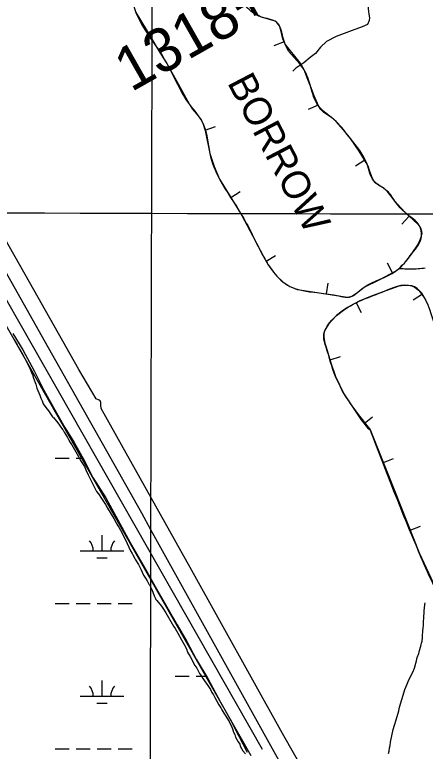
# Model space of a CAD drawing. Extents: x 3177185 to 3215018, y 812988 to 838321.
# Drawn here: x 3191526 to 3192464, y 823203 to 824888 of the extents above; entities that cross this region are included whole.
import ezdxf

# ---------------------------------------------------------------- set-up
doc = ezdxf.new("R2010")
doc.units = 0
for name, color, linetype in [('V-BORW-IDEN', 7, 'Continuous'), ('V-BORW-LINE', 7, 'Continuous'), ('V-GRID-MAJR', 7, 'Continuous'), ('V-ROAD-CNTR', 7, 'Continuous'), ('V-SITE-VEGE', 7, 'Continuous'), ('V-SURV-IDEN', 7, 'Continuous'), ('V-TOPO-SHOR', 7, 'Continuous'), ('V-WETL-SWMP', 7, 'Continuous')]:
    doc.layers.add(name, color=color, linetype=linetype)

msp = doc.modelspace()

# ---------------------------------------------------------------- linework, layer by layer
at = {"layer": 'V-BORW-LINE'}
for p, q in [((3192141.393, 824826.683), (3192118.318, 824817.063)), ((3191878.114, 824768.1410000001), (3191899.912, 824780.382)), ((3192219.4050000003, 824681.253), (3192196.271, 824671.777)), ((3191961.091, 824624.482), (3191984.752, 824632.554)), ((3192325.955, 824555.2490000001), (3192304.648, 824542.172)), ((3192019.5810000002, 824470.2930000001), (3192040.762, 824483.573)), ((3192427.292, 824427.59), (3192410.443, 824409.121)), ((3192100.417, 824324.746), (3192121.884, 824337.56)), ((3192389.773, 824297.56), (3192378.131, 824319.684)), ((3192238.593, 824249.332), (3192242.319, 824274.0530000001)), ((3192457.967, 824248.6140000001), (3192437.011, 824234.982)), ((3192306.193, 824228.922), (3192318.008, 824206.89)), ((3192246.517, 824098.697), (3192270.387, 824106.13)), ((3192324.406, 823952.698), (3192343.738, 823968.55)), ((3192368.48, 823863.686), (3192391.6720000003, 823873.02)), ((3192430.092, 823708.898), (3192453.344, 823718.082))]:
    msp.add_line(p, q, dxfattribs=at)
for points in [[(3191802.893, 824893.649), (3191825.791, 824854.311), (3191849.315, 824815.3250000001), (3191861.311, 824796.055), (3191873.268, 824776.77), (3191899.437, 824730.169), (3191924.8910000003, 824683.207), (3191932.312, 824672.331), (3191944.924, 824656.929), (3191950.79, 824648.942), (3191955.682, 824640.335), (3191961.438, 824623.463), (3191971.713, 824570.679), (3191981.668, 824540.805), (3191994.094, 824511.837), (3192019.5330000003, 824470.3690000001), (3192045.276, 824429.312), (3192070.1550000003, 824381.653), (3192094.983, 824333.85), (3192105.403, 824316.394), (3192117.092, 824299.568), (3192125.1580000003, 824289.786), (3192139.005, 824277.0040000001), (3192155.042, 824266.5210000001), (3192165.957, 824261.595), (3192171.576, 824259.8640000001), (3192177.336, 824258.661), (3192221.954, 824251.84), (3192266.571, 824245.115), (3192276.3370000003, 824243.235), (3192286.058, 824241.897), (3192291.34, 824242.404), (3192299.951, 824246.201), (3192324.307, 824264.608), (3192360.5870000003, 824282.201), (3192396.65, 824301.179), (3192407.774, 824309.734), (3192421.749, 824325.3960000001), (3192434.708, 824342.899), (3192447.285, 824362.088), (3192452.24, 824371.969), (3192456.06, 824382.018), (3192456.992, 824387.93), (3192456.661, 824392.655), (3192454.583, 824399.6240000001), (3192452.862, 824402.833), (3192450.704, 824405.7220000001), (3192435.805, 824419.824), (3192421.022, 824433.31), (3192407.884, 824447.405), (3192394.965, 824461.7170000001), (3192386.112, 824473.164), (3192377.455, 824484.7270000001), (3192370.258, 824491.023), (3192357.532, 824498.556), (3192351.585, 824502.735), (3192346.703, 824507.969), (3192341.919, 824517.18), (3192337.146, 824532.232), (3192334.609, 824539.6780000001), (3192331.216, 824546.6780000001), (3192312.982, 824576.385), (3192293.082, 824605.185), (3192277.036, 824625.013), (3192260.259, 824644.0800000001), (3192249.8850000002, 824653.022)], [(3192249.8850000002, 824653.022), (3192232.624, 824664.931), (3192225.2260000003, 824671.751), (3192219.879, 824680.096), (3192210.6550000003, 824702.618), (3192201.764, 824725.246), (3192194.538, 824743.696), (3192187.275, 824762.1290000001), (3192178.468, 824778.0210000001), (3192143.806, 824820.8960000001), (3192138.727, 824833.079), (3192134.148, 824853.208), (3192130.693, 824862.671), (3192124.899, 824870.849), (3192120.969, 824873.873), (3192087.455, 824883.493), (3192070.43, 824894.555)], [(3192467.754, 824230.1900000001), (3192462.112, 824242.243), (3192456.491, 824250.883), (3192446.075, 824261.6730000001), (3192440.066, 824265.508), (3192433.582, 824267.9450000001), (3192416.849, 824269.091), (3192403.916, 824266.938), (3192365.528, 824253.63), (3192339.108, 824243.687), (3192313.008, 824232.577), (3192286.514, 824218.3690000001), (3192273.998, 824209.811), (3192261.659, 824199.732), (3192250.451, 824189.012), (3192242.9590000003, 824180.3250000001)], [(3192242.9590000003, 824180.3250000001), (3192234.754, 824166.36), (3192232.614, 824158.997), (3192232.149, 824151.405), (3192232.845, 824145.559), (3192234.859, 824136.724), (3192237.406, 824127.957), (3192247.975, 824094.017), (3192259.282, 824060.314), (3192278.285, 824020.79), (3192317.499, 823961.122), (3192332.1180000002, 823943.2930000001), (3192336.201, 823939.839), (3192337.378, 823940.962)], [(3192337.378, 823940.962), (3192394.177, 823799.838), (3192450.6750000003, 823656.781), (3192482.6950000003, 823588.069), (3192515.512, 823519.68), (3192537.107, 823479.862), (3192558.6750000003, 823439.9550000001), (3192581.161, 823387.567), (3192600.502, 823333.666), (3192610.71, 823300.028), (3192618.286, 823265.887), (3192619.163, 823259.2980000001), (3192619.292, 823249.2760000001), (3192618.13, 823239.322), (3192609.906, 823203.8520000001), (3192603.901, 823186.684)]]:
    msp.add_lwpolyline(points, dxfattribs=at)
for points in [[(3191622.742, 825105.902), (3191651.35, 825110.314), (3191667.156, 825113.006), (3191677.221, 825125.539), (3191677.722, 825150.566), (3191695.35, 825181.5160000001), (3191705.5, 825170.326), (3191714.339, 825135.098), (3191723.386, 825084.675), (3191731.308, 825045.7220000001), (3191772.33, 824986.109), (3191802.893, 824893.649), (3191849.315, 824815.3250000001), (3191873.268, 824776.77), (3191924.8910000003, 824683.207), (3191955.682, 824640.335), (3191971.713, 824570.679), (3191994.094, 824511.837), (3192045.276, 824429.312), (3192094.983, 824333.85), (3192117.092, 824299.568), (3192155.042, 824266.5210000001), (3192177.336, 824258.661), (3192266.571, 824245.115), (3192286.058, 824241.897), (3192324.307, 824264.608), (3192396.65, 824301.179), (3192434.708, 824342.899), (3192456.06, 824382.018), (3192450.704, 824405.7220000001), (3192421.022, 824433.31), (3192394.965, 824461.7170000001), (3192377.455, 824484.7270000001), (3192346.703, 824507.969), (3192331.216, 824546.6780000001), (3192293.082, 824605.185), (3192260.259, 824644.0800000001), (3192219.879, 824680.096), (3192201.764, 824725.246), (3192187.275, 824762.1290000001), (3192143.806, 824820.8960000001), (3192124.899, 824870.849), (3192087.455, 824883.493), (3192054.219, 824907.3470000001), (3192037.745, 824927.074), (3192024.92, 824966.971), (3192036.738, 824992.503), (3192028.268, 825028.694), (3192017.0500000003, 825096.507), (3192020.132, 825119.187), (3191979.876, 825102.763), (3191904.674, 825120.359), (3191884.778, 825160.417), (3191856.59, 825186.583), (3191829.8340000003, 825193.435), (3191792.1040000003, 825190.479), (3191767.572, 825182.299), (3191746.186, 825196.519), (3191708.966, 825215.9550000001), (3191653.22, 825256.4130000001), (3191581.071, 825322.769), (3191560.504, 825333.3640000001), (3191548.612, 825328.9180000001), (3191546.248, 825313.436), (3191549.606, 825293.383), (3191556.295, 825252.1), (3191563.607, 825201.578), (3191570.9250000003, 825166.593), (3191578.702, 825133.47), (3191589.546, 825110.126), (3191619.514, 825098.138), (3191635.418, 825108.18)], [(3192337.378, 823940.962), (3192450.6750000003, 823656.781), (3192515.512, 823519.68), (3192558.6750000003, 823439.9550000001), (3192600.502, 823333.666), (3192618.286, 823265.887), (3192618.13, 823239.322), (3192596.168, 823170.181), (3192570.128, 823124.488), (3192544.017, 823075.534), (3192525.992, 822981.143), (3192537.224, 822863.983), (3192568.707, 822741.261), (3192590.757, 822730.8420000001), (3192607.4760000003, 822734.716), (3192633.424, 822744.133), (3192790.951, 822860.632), (3192848.333, 822890.561), (3193002.452, 822993.536), (3193064.424, 823044.062), (3193073.036, 823061.536), (3193065.488, 823079.991), (3193018.025, 823160.412), (3192976.418, 823287.094), (3192938.651, 823343.995), (3192918.919, 823400.677), (3192904.153, 823413.796), (3192761.5640000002, 823666.5040000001), (3192731.482, 823699.6780000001), (3192695.518, 823756.439), (3192584.431, 823915.904), (3192476.548, 824206.74), (3192467.754, 824230.1900000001), (3192433.582, 824267.9450000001), (3192365.528, 824253.63), (3192313.008, 824232.577), (3192261.659, 824199.732), (3192232.149, 824151.405), (3192237.406, 824127.957), (3192259.282, 824060.314), (3192337.378, 823940.962)]]:
    msp.add_spline(points, degree=3, dxfattribs=at)
at = {"layer": 'V-GRID-MAJR'}
for points in [[(3191823.847, 818374.883), (3191838.828, 824434.0750000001), (3191853.818, 830496.351), (3191868.808, 836558.667), (3191868.816, 836561.711)], [(3181368.912, 824461.486), (3186603.869, 824447.399), (3191838.828, 824434.0750000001), (3197073.789, 824421.511), (3202308.752, 824409.709), (3207543.717, 824398.669), (3212778.683, 824388.39), (3212778.684, 824388.39)]]:
    msp.add_spline(points, degree=3, dxfattribs=at)
at = {"layer": 'V-ROAD-CNTR'}
for points in [[(3192066.4598301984, 823192.2505880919), (3191276.6574098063, 824578.8238149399), (3190952.709057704, 825148.1706762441), (3190661.6016399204, 825652.093668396), (3190618.270726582, 825760.0984523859), (3190608.050747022, 825817.1313383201), (3190587.1187888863, 825858.73625511)], [(3192092.527778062, 823207.0985583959), (3191302.729357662, 824593.665785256), (3190978.735005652, 825163.0926464), (3190688.647585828, 825665.247642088), (3190647.2586686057, 825768.41643575), (3190636.810689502, 825826.7173191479), (3190627.045709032, 825846.1272803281)]]:
    msp.add_lwpolyline(points, dxfattribs=at)
at = {"layer": 'V-SITE-VEGE'}
for p, q in [((3191524.419, 824145.6240000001), (3191526.839, 824140.7639999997)), ((3191526.839, 824140.7639999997), (3191531.275, 824133.066)), ((3191531.275, 824133.066), (3191533.694, 824128.2059999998)), ((3191533.694, 824128.2059999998), (3191544.182, 824110.3819999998)), ((3191544.182, 824110.3819999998), (3191549.021, 824101.8769999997)), ((3191549.021, 824101.8769999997), (3191549.826, 824099.8539999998)), ((3191549.826, 824099.8539999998), (3191552.65, 824094.99)), ((3191552.65, 824094.99), (3191555.069, 824089.3209999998)), ((3191555.069, 824089.3209999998), (3191559.099, 824081.219)), ((3191559.099, 824081.219), (3191562.323, 824073.121)), ((3191562.323, 824073.121), (3191564.742, 824067.4500000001)), ((3191564.742, 824067.4500000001), (3191565.948, 824065.0189999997)), ((3191565.948, 824065.0189999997), (3191568.764, 824056.518)), ((3191568.764, 824056.518), (3191573.595, 824042.7490000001)), ((3191573.595, 824042.7490000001), (3191576.409, 824033.437)), ((3191576.409, 824033.437), (3191583.2600000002, 824017.643)), ((3191583.2600000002, 824017.643), (3191585.271, 824010.7589999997)), ((3191585.271, 824010.7589999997), (3191588.093, 824004.685)), ((3191588.093, 824004.685), (3191590.913, 823998.2049999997)), ((3191590.913, 823998.2049999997), (3191596.967, 823989.6939999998)), ((3191596.967, 823989.6939999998), (3191603.021, 823981.5920000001)), ((3191603.021, 823981.5920000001), (3191611.899, 823968.22)), ((3191611.899, 823968.22), (3191613.515, 823966.5979999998)), ((3191613.515, 823966.5979999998), (3191614.324, 823966.5979999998)), ((3191614.324, 823966.5979999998), (3191624.0130000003, 823954.845)), ((3191624.0130000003, 823954.845), (3191628.0470000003, 823949.172)), ((3191628.0470000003, 823949.172), (3191629.663, 823947.1460000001)), ((3191629.663, 823947.1460000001), (3191634.906, 823939.0430000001)), ((3191634.906, 823939.0430000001), (3191636.524, 823937.421)), ((3191636.524, 823937.421), (3191638.539, 823933.372)), ((3191638.539, 823933.372), (3191646.207, 823921.2170000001)), ((3191646.207, 823921.2170000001), (3191648.624, 823916.3569999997)), ((3191648.624, 823916.3569999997), (3191652.6580000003, 823909.469)), ((3191652.6580000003, 823909.469), (3191655.886, 823904.202)), ((3191655.886, 823904.202), (3191671.213, 823877.4669999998)), ((3191671.213, 823877.4669999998), (3191674.844, 823871.3910000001)), ((3191674.844, 823871.3910000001), (3191676.052, 823868.1509999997)), ((3191676.052, 823868.1509999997), (3191684.928, 823854.78)), ((3191684.928, 823854.78), (3191688.1520000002, 823846.682)), ((3191688.1520000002, 823846.682), (3191693.794, 823835.3399999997)), ((3191693.794, 823835.3399999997), (3191703.066, 823815.4949999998)), ((3191703.066, 823815.4949999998), (3191706.697, 823809.824)), ((3191706.697, 823809.824), (3191707.9050000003, 823806.582)), ((3191707.9050000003, 823806.582), (3191712.744, 823797.6709999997)), ((3191712.744, 823797.6709999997), (3191716.781, 823791.998)), ((3191716.781, 823791.998), (3191724.043, 823781.463)), ((3191724.043, 823781.463), (3191731.305, 823770.1190000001)), ((3191731.305, 823770.1190000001), (3191732.919, 823767.2849999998)), ((3191732.919, 823767.2849999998), (3191737.761, 823759.587)), ((3191737.761, 823759.587), (3191752.2830000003, 823735.281)), ((3191752.2830000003, 823735.281), (3191757.526, 823725.5589999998)), ((3191757.526, 823725.5589999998), (3191761.561, 823719.0769999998)), ((3191761.561, 823719.0769999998), (3191763.578, 823715.432)), ((3191763.578, 823715.432), (3191767.608, 823708.5439999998)), ((3191767.608, 823708.5439999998), (3191773.255, 823697.608)), ((3191773.255, 823697.608), (3191782.526, 823678.1659999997)), ((3191782.526, 823678.1659999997), (3191790.185, 823661.5609999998)), ((3191790.185, 823661.5609999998), (3191793.8140000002, 823655.485)), ((3191793.8140000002, 823655.485), (3191795.426, 823652.247)), ((3191795.426, 823652.247), (3191800.2660000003, 823643.7369999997)), ((3191800.2660000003, 823643.7369999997), (3191801.88, 823641.306)), ((3191801.88, 823641.306), (3191808.335, 823629.9649999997)), ((3191808.335, 823629.9649999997), (3191813.576, 823619.837)), ((3191813.576, 823619.837), (3191820.428, 823606.066)), ((3191820.428, 823606.066), (3191824.463, 823599.179)), ((3191824.463, 823599.179), (3191828.497, 823593.1029999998)), ((3191828.497, 823593.1029999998), (3191832.5300000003, 823585.406)), ((3191832.5300000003, 823585.406), (3191833.74, 823583.7859999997)), ((3191833.74, 823583.7859999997), (3191836.968, 823577.7099999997)), ((3191836.968, 823577.7099999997), (3191838.981, 823573.2549999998)), ((3191838.981, 823573.2549999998), (3191844.619, 823558.6779999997)), ((3191844.619, 823558.6779999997), (3191847.845, 823552.196)), ((3191847.845, 823552.196), (3191848.2460000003, 823550.1719999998)), ((3191848.2460000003, 823550.1719999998), (3191850.2660000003, 823548.1449999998)), ((3191850.2660000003, 823548.1449999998), (3191861.165, 823534.7710000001)), ((3192462.804, 823530.571), (3192463.627, 823539.066)), ((3192463.627, 823539.066), (3192464.444, 823542.707)), ((3191861.165, 823534.7710000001), (3191864.395, 823530.3149999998)), ((3191864.395, 823530.3149999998), (3191871.253, 823519.7799999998)), ((3191871.253, 823519.7799999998), (3191889.001, 823489.3979999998)), ((3192460.742, 823510.748), (3192461.569, 823520.456)), ((3192461.569, 823520.456), (3192461.983, 823523.2880000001)), ((3192461.983, 823523.2880000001), (3192461.985, 823525.312)), ((3192461.985, 823525.312), (3192462.804, 823530.571)), ((3192460.299, 823490.109), (3192460.322, 823501.844)), ((3192460.322, 823501.844), (3192460.733, 823505.485)), ((3192460.733, 823505.485), (3192460.742, 823510.748)), ((3191889.001, 823489.3979999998), (3191892.231, 823484.1309999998)), ((3192458.659, 823478.378), (3192459.886, 823485.658)), ((3192459.886, 823485.658), (3192460.299, 823490.109)), ((3191892.231, 823484.1309999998), (3191895.457, 823478.46)), ((3191895.457, 823478.46), (3191898.684, 823473.192)), ((3191898.684, 823473.192), (3191907.1550000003, 823458.2049999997)), ((3192458.223, 823463.001), (3192458.239, 823469.881)), ((3192458.239, 823469.881), (3192458.651, 823474.331)), ((3192458.651, 823474.331), (3192458.659, 823478.378)), ((3191907.1550000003, 823458.2049999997), (3191909.975, 823452.534)), ((3191909.975, 823452.534), (3191913.203, 823447.269)), ((3192455.773, 823450.461), (3192456.9960000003, 823454.506)), ((3192456.9960000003, 823454.506), (3192458.223, 823463.001)), ((3191913.203, 823447.269), (3191918.04, 823437.1409999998)), ((3191918.04, 823437.1409999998), (3191920.856, 823429.8519999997)), ((3192451.29, 823433.473), (3192454.143, 823443.181)), ((3192454.143, 823443.181), (3192454.958, 823447.226)), ((3192454.958, 823447.226), (3192455.773, 823450.461)), ((3191920.856, 823429.8519999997), (3191926.912, 823419.725)), ((3191926.912, 823419.725), (3191937.7970000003, 823399.4719999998)), ((3192445.861, 823417.171), (3192446, 823417.702)), ((3192446, 823417.702), (3192449.66, 823427.0040000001)), ((3192449.66, 823427.0040000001), (3192451.29, 823433.473)), ((3192439.883, 823393.029), (3192443.143, 823404.3549999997)), ((3192443.143, 823404.3549999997), (3192443.9620000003, 823410.018)), ((3192443.9620000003, 823410.018), (3192445.861, 823417.171)), ((3191937.7970000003, 823399.4719999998), (3191941.832, 823392.9899999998)), ((3191941.832, 823392.9899999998), (3191948.285, 823381.243)), ((3192426.481, 823366.346), (3192436.225, 823384.135)), ((3192436.225, 823384.135), (3192439.883, 823393.029)), ((3191948.285, 823381.243), (3191952.725, 823374.759)), ((3191952.725, 823374.759), (3191955.951, 823369.4940000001)), ((3191955.951, 823369.4940000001), (3191966.848, 823353.2879999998)), ((3191966.848, 823353.2879999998), (3191972.9, 823343.9670000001)), ((3192419.974, 823349.3640000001), (3192422.0100000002, 823355.025)), ((3192422.0100000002, 823355.025), (3192426.481, 823366.346)), ((3191972.9, 823343.9670000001), (3191976.529, 823337.4879999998)), ((3191976.529, 823337.4879999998), (3191980.16, 823331.8150000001)), ((3192405.7260000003, 823303.665), (3192416.312, 823338.85)), ((3192416.312, 823338.85), (3192417.9420000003, 823344.107)), ((3192417.9420000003, 823344.107), (3192419.974, 823349.3640000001)), ((3191980.16, 823331.8150000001), (3191983.3880000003, 823326.144)), ((3191983.3880000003, 823326.144), (3191992.257, 823309.1309999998)), ((3191992.257, 823309.1309999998), (3191996.696, 823302.2440000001)), ((3191996.696, 823302.2440000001), (3191999.52, 823297.384)), ((3192403.688, 823295.5750000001), (3192405.7260000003, 823303.665)), ((3191999.52, 823297.384), (3192003.958, 823290.4940000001)), ((3192003.958, 823290.4940000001), (3192006.782, 823285.634)), ((3192006.782, 823285.634), (3192016.061, 823271.05)), ((3192397.983, 823274.542), (3192403.688, 823295.5750000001)), ((3192016.061, 823271.05), (3192018.478, 823265.38)), ((3192393.915, 823262.8150000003), (3192397.983, 823274.542)), ((3192018.478, 823265.38), (3192021.3000000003, 823260.1140000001)), ((3192021.3000000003, 823260.1140000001), (3192024.1180000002, 823252.014)), ((3192024.1180000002, 823252.014), (3192026.131, 823246.751)), ((3192384.5330000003, 823223.582), (3192391.065, 823253.11)), ((3192391.065, 823253.11), (3192393.915, 823262.8150000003)), ((3192026.131, 823246.751), (3192028.548, 823241.0779999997)), ((3192028.548, 823241.0779999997), (3192030.561, 823235.411)), ((3192030.561, 823235.411), (3192036.611, 823224.88)), ((3192036.611, 823224.88), (3192040.242, 823218.8019999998)), ((3192040.242, 823218.8019999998), (3192041.448, 823214.7529999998)), ((3192382.893, 823210.637), (3192383.71, 823215.8960000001)), ((3192383.71, 823215.8960000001), (3192384.5330000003, 823223.582)), ((3192041.448, 823214.7529999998), (3192047.498, 823204.2219999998)), ((3192047.498, 823204.2219999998), (3192053.153, 823197.331)), ((3192380.036, 823197.689), (3192382.068, 823202.948)), ((3192382.068, 823202.948), (3192382.893, 823210.637))]:
    msp.add_line(p, q, dxfattribs=at)
at = {"layer": 'V-TOPO-SHOR'}
for points in [[(3192423.089, 825013.647), (3192392.406, 824991.985), (3192368.301, 824976.541), (3192355.481, 824963.6), (3192345.3510000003, 824949.309), (3192338.9390000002, 824940.564), (3192331.992, 824918.015), (3192333.983, 824901.68), (3192335.308, 824889.892), (3192336.975, 824881.3030000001), (3192336.1210000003, 824875.0750000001), (3192332.4, 824865.822), (3192320.267, 824860.962), (3192296.85, 824852.588), (3192260.455, 824838.514), (3192238.21, 824827.274), (3192224.5500000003, 824814.167), (3192213.241, 824799.876), (3192201.1, 824790.134), (3192186.43, 824778.376), (3192168.73, 824765.781), (3192161.7090000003, 824759.566)], [(3192259.546, 823029.245), (3192137.606, 823243.794), (3191926.47, 823623.393), (3191723.0700000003, 823986.915), (3191722.204, 823995.5650000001), (3191722.214, 824000.861), (3191721.34, 824004.5700000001), (3191718.872, 824006.694), (3191711.815, 824009.357), (3191671.866, 824076.693), (3191559.431, 824276.743), (3191388.575, 824577.181), (3191236.5500000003, 824847.392), (3191197.134, 824915.963)], [(3191166.375, 824893.601), (3191222.156, 824796.929), (3191370.845, 824536.608), (3191592.021, 824144.631), (3191815.13, 823748.2390000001), (3191836.069, 823710.242), (3191893.427, 823607.566), (3192133.24, 823174.598)], [(3192430.749, 824306.042), (3192426.481, 824306.085), (3192422.217, 824306.2000000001), (3192417.955, 824306.388), (3192413.697, 824306.648), (3192409.4450000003, 824306.98), (3192406.404, 824307.265)], [(3192464.34, 824308.297), (3192460.555, 824307.785), (3192456.312, 824307.318), (3192452.062, 824306.925), (3192447.806, 824306.603), (3192443.5470000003, 824306.353), (3192439.281, 824306.177), (3192435.015, 824306.073), (3192430.749, 824306.042)]]:
    msp.add_lwpolyline(points, dxfattribs=at)
at = {"layer": 'V-WETL-SWMP'}
for p, q in [((3191618.3195443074, 823873.9547680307), (3191650.3195234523, 823873.9547680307)), ((3191666.3195130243, 823873.9547680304), (3191681.5447706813, 823873.9547680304)), ((3191725.1637001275, 823661.3508597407), (3191725.163661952, 823697.3508442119)), ((3191675.163732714, 823661.3508597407), (3191775.1636675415, 823661.3508597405)), ((3191713.1637243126, 823645.9198663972), (3191737.1637086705, 823645.9198663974)), ((3191618.3198970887, 823541.2799115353), (3191650.3198762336, 823541.2799115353)), ((3191666.3198658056, 823541.2799115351), (3191698.319844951, 823541.2799115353)), ((3191714.3198345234, 823541.2799115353), (3191746.319813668, 823541.2799115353)), ((3191762.3198032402, 823541.2799115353), (3191794.319782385, 823541.2799115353)), ((3191892.2278947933, 823375.105983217), (3191924.227873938, 823375.105983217)), ((3191940.22786351, 823375.1059832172), (3191963.5731662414, 823375.105983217)), ((3191725.164052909, 823328.6760032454), (3191725.1640147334, 823364.6759877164)), ((3191675.1640854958, 823328.6760032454), (3191775.1640203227, 823328.6760032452)), ((3191713.164077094, 823313.2450099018), (3191737.164061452, 823313.245009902)), ((3191618.32024987, 823208.6050550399), (3191650.320229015, 823208.6050550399)), ((3191666.320218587, 823208.6050550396), (3191698.320197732, 823208.6050550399)), ((3191714.3201873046, 823208.6050550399), (3191746.320166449, 823208.6050550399)), ((3191762.3201560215, 823208.6050550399), (3191794.3201351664, 823208.6050550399))]:
    msp.add_line(p, q, dxfattribs=at)
msp.add_lwpolyline([(3191521.636, 824159.229), (3191544.4560000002, 824121.438), (3191569.7290000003, 824073.21), (3191592.183, 824029.142), (3191614.468, 823989.584), (3191640.1, 823944.007), (3191661.6010000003, 823909.665), (3191682.2120000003, 823872.762), (3191703.8710000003, 823829.403), (3191733.744, 823782.846), (3191761.136, 823732.758), (3191789.673, 823680.81), (3191823.5870000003, 823621.339), (3191846.84, 823579.745), (3191873.267, 823533.46), (3191897.053, 823492.572), (3191919.075, 823454.074), (3191940.563, 823413.633), (3191966.994, 823369.381), (3191995.969, 823315.488), (3192019.752, 823273.452), (3192038.066, 823237.348), (3192056.822, 823200.8910000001)], dxfattribs=at)
for centre, radius, start, end in [((3191669.920799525, 823661.8256627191), 35.24628790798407, 359.22817978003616, 40.77183811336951), ((3191780.4065997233, 823661.8256627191), 35.24628790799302, 139.2281771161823, 180.77183544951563), ((3191669.9211523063, 823329.1508062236), 35.24628790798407, 359.22817978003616, 40.77183811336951), ((3191780.4069525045, 823329.1508062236), 35.24628790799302, 139.2281771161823, 180.77183544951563)]:
    msp.add_arc(centre, radius, start, end, dxfattribs=at)

# ---------------------------------------------------------------- texts
at = {"layer": 'V-BORW-IDEN'}
msp.add_text('BORROW', height=64.00000200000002, rotation=297.59200806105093, dxfattribs=at).set_placement((3192010.7196525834, 824733.1077254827))
at = {"layer": 'V-SURV-IDEN'}
msp.add_text('1318+04.2', height=100.00000000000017, rotation=29.554444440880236, dxfattribs=at).set_placement((3191791.680614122, 824710.2921992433))

doc.saveas('drawing.dxf')
